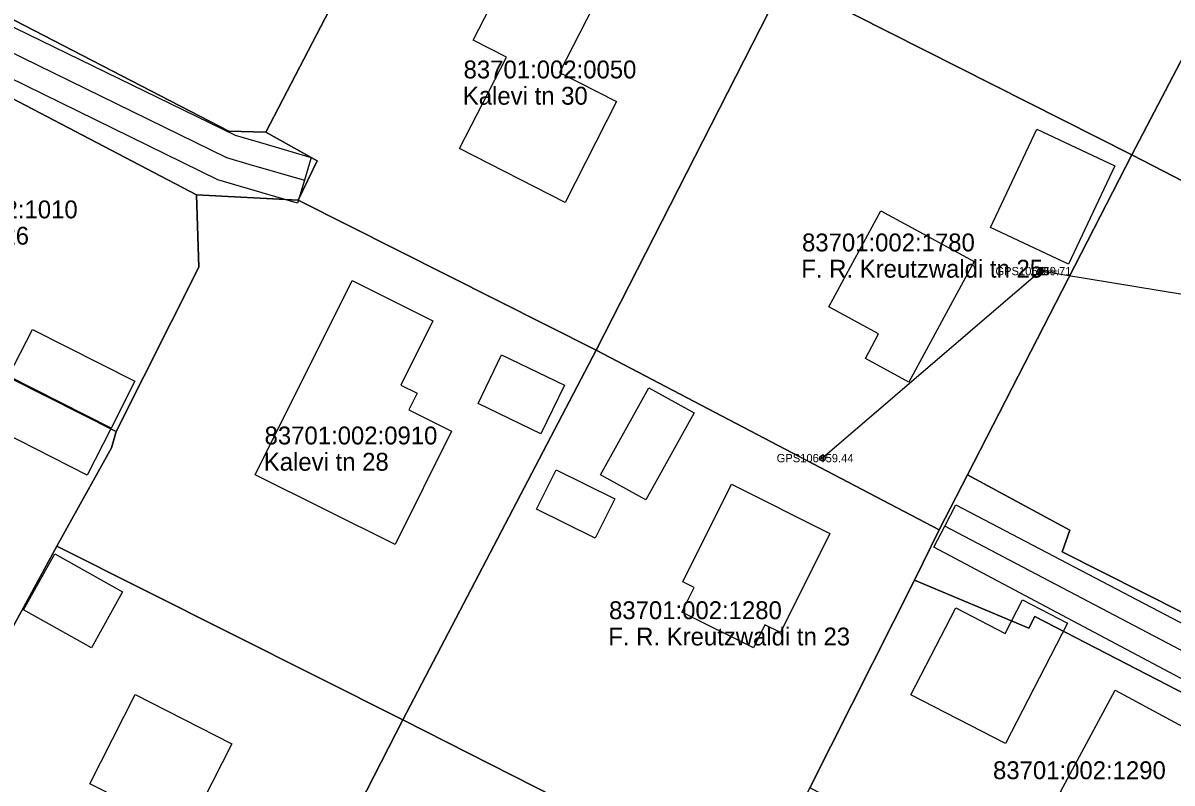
# Model space of a CAD drawing. Extents: x 580119 to 583377, y 6518915 to 6520820.
# Drawn here: x 581504.1 to 581600.6, y 6520162.8 to 6520226.6 of the extents above; entities that cross this region are included whole.
import ezdxf

# ---------------------------------------------------------------- set-up
doc = ezdxf.new("R2010")
doc.units = 0
for name, color, linetype in [('ELRAJATISMP', 7, 'Continuous'), ('Hoone Elu- või ühiskondlik hoone', 7, 'Continuous'), ('Hoone Kõrval- või tootmishoone', 7, 'Continuous'), ('L_AADRESS', 7, 'Continuous'), ('MAAMUDEL', 7, 'Continuous'), ('MOOTKORG-EH2000', 7, 'Continuous'), ('MOOTMPUNKT', 7, 'Continuous'), ('MOOTNR', 7, 'Continuous'), ('MPOHULIIN', 7, 'Continuous'), ('PIIR', 7, 'Continuous'), ('POST', 7, 'Continuous'), ('Tee Liiklusala', 7, 'Continuous'), ('Tee Tänav Kruuskate', 7, 'Continuous'), ('TUNNUS', 7, 'Continuous')]:
    doc.layers.add(name, color=color, linetype=linetype)

msp = doc.modelspace()

# ---------------------------------------------------------------- linework, layer by layer
at = {"layer": 'ELRAJATISMP'}
for p, q in [((581589.382, 6520206.077), (581589.382, 6520205.48)), ((581589.653, 6520206.077), (581589.653, 6520205.48))]:
    msp.add_line(p, q, dxfattribs=at)
msp.add_lwpolyline([(581588.92, 6520206.077), (581590.115, 6520206.077), (581590.115, 6520205.48), (581588.92, 6520205.48)], close=True, dxfattribs=at)
at = {"layer": 'Hoone Elu- või ühiskondlik hoone'}
for points in [[(581553.942, 6520220.01), (581549.621, 6520211.545), (581540.775, 6520216.062), (581544.698, 6520223.743), (581541.926, 6520225.158), (581545.709, 6520232.58), (581552.556, 6520229.093), (581549.17, 6520222.439)], [(581571.75, 6520202.781), (581576.13, 6520210.841), (581583.96, 6520206.591), (581578.47, 6520196.471), (581574.83, 6520198.452), (581575.94, 6520200.502)], [(581540.104, 6520192.346), (581535.37, 6520182.839), (581523.633, 6520188.67), (581531.752, 6520204.98), (581538.525, 6520201.619), (581535.842, 6520196.212), (581537.209, 6520195.533), (581536.508, 6520194.13)], [(581571.857, 6520183.763), (581567.692, 6520175.435), (581566.393, 6520176.078), (581565.433, 6520174.163), (581559.434, 6520177.161), (581560.47, 6520179.224), (581559.497, 6520179.705), (581563.596, 6520187.894)], [(581604.35, 6520165.985), (581597.897, 6520154.009), (581593.562, 6520156.341), (581595.422, 6520159.794), (581591.206, 6520162.073), (581595.796, 6520170.595)], [(581522.566, 6520157.552), (581517.928, 6520148.438), (581507.038, 6520153.985), (581511.137, 6520162.046), (581509.745, 6520162.757), (581513.559, 6520170.238), (581521.666, 6520166.106), (581518.401, 6520159.68)]]:
    msp.add_lwpolyline(points, close=True, dxfattribs=at)
at = {"layer": 'Hoone Kõrval- või tootmishoone'}
for points in [[(581595.754, 6520214.608), (581591.871, 6520206.359), (581585.333, 6520209.437), (581589.216, 6520217.686)], [(581511.532, 6520192.6), (581502.926, 6520196.95), (581504.922, 6520200.89), (581513.527, 6520196.541)], [(581542.321, 6520194.662), (581544.294, 6520198.751), (581549.579, 6520196.204), (581547.596, 6520192.112)], [(581511.532, 6520192.6), (581509.533, 6520188.652), (581500.929, 6520193.006), (581502.926, 6520196.95)], [(581552.613, 6520188.69), (581556.663, 6520195.98), (581560.453, 6520193.879), (581556.403, 6520186.589)], [(581547.236, 6520185.813), (581548.882, 6520189.111), (581553.79, 6520186.659), (581552.144, 6520183.36)], [(581512.501, 6520178.864), (581509.878, 6520174.17), (581504.174, 6520177.356), (581506.811, 6520182.049)], [(581591.796, 6520176.235), (581586.578, 6520166.126), (581578.641, 6520170.222), (581582.408, 6520177.522), (581586.569, 6520175.375), (581588.019, 6520178.184)]]:
    msp.add_lwpolyline(points, close=True, dxfattribs=at)
at = {"layer": 'MOOTMPUNKT'}
for centre in [(581589.517, 6520205.779), (581571.23, 6520190.084)]:
    msp.add_circle(centre, 0.1, dxfattribs=at)
at = {"layer": 'MPOHULIIN'}
msp.add_lwpolyline([(581646.487, 6520186.542), (581631.562, 6520198.859), (581589.517, 6520205.779), (581571.23, 6520190.084)], dxfattribs=at)
at = {"layer": 'PIIR'}
for points in [[(581583.97, 6520261.52), (581613.05, 6520246.51), (581610.93, 6520241.82), (581597.19, 6520215.53), (581568.1, 6520230.26)], [(581501.63, 6520251.7), (581524.76, 6520240.58), (581534.1, 6520235.9), (581524.52, 6520217.43), (581521.41, 6520217.52), (581491.96, 6520232.77)], [(581528.82, 6520215.03), (581524.52, 6520217.43), (581534.1, 6520235.9), (581538.79, 6520244.96), (581568.1, 6520230.26), (581552.23, 6520199.15), (581527.23, 6520211.74)], [(581610.93, 6520241.82), (581626.48, 6520236.22), (581644.07, 6520226.93), (581629.73, 6520198.75), (581597.19, 6520215.53)], [(581568.1, 6520230.26), (581597.19, 6520215.53), (581583.39, 6520188.69), (581581.01, 6520184.07), (581552.23, 6520199.15)], [(581489.39, 6520227.52), (581518.7, 6520212.19), (581518.89, 6520206.11), (581511.97, 6520192.31), (581479.44, 6520208.7)], [(581591.98, 6520184.05), (581583.39, 6520188.69), (581597.19, 6520215.53), (581629.73, 6520198.75), (581615.13, 6520170.23), (581591.33, 6520182.23)], [(581511.56, 6520190.95), (581511.97, 6520192.31), (581518.89, 6520206.11), (581518.7, 6520212.19), (581527.23, 6520211.74), (581552.23, 6520199.15), (581536.02, 6520168.12), (581506.99, 6520182.7)], [(581479.44, 6520208.7), (581511.97, 6520192.31), (581511.56, 6520190.95), (581506.99, 6520182.7), (581502.29, 6520174.04), (581470.18, 6520190.74)], [(581552.23, 6520199.15), (581581.01, 6520184.07), (581578.96, 6520179.83), (581570.17, 6520162.41), (581565.37, 6520153.21), (581536.02, 6520168.12)], [(581493.4, 6520156.77), (581502.29, 6520174.04), (581506.99, 6520182.7), (581536.02, 6520168.12), (581520.24, 6520137.28), (581491.13, 6520152.34)], [(581578.96, 6520179.83), (581588.53, 6520175.82), (581589.04, 6520176.78), (581612.12, 6520164.88), (581602.44, 6520145.86), (581570.17, 6520162.41)], [(581536.02, 6520168.12), (581565.37, 6520153.21), (581560.56, 6520143.98), (581551.54, 6520126.53), (581549.16, 6520122.21), (581520.24, 6520137.28)]]:
    msp.add_lwpolyline(points, close=True, dxfattribs=at)
for points in [[(581491.96, 6520232.77), (581521.41, 6520217.52), (581524.52, 6520217.43), (581528.82, 6520215.03), (581527.23, 6520211.74), (581518.7, 6520212.19), (581489.39, 6520227.52)], [(581612.12, 6520164.88), (581589.04, 6520176.78), (581588.53, 6520175.82), (581578.96, 6520179.83), (581581.01, 6520184.07), (581583.39, 6520188.69), (581591.98, 6520184.05), (581591.33, 6520182.23), (581615.13, 6520170.23)]]:
    msp.add_lwpolyline(points, dxfattribs=at)
at = {"layer": 'POST'}
for centre in [(581589.517, 6520205.779), (581571.23, 6520190.084)]:
    msp.add_circle(centre, 0.25, dxfattribs=at)
at = {"layer": 'Tee Liiklusala'}
for points in [[(581491.478, 6520232.04), (581521.93, 6520217.192), (581524.08, 6520216.562), (581528.31, 6520215.323), (581527.748, 6520213.404), (581527.186, 6520211.485), (581522.385, 6520212.891), (581520.478, 6520213.45), (581489.717, 6520228.51)], [(581612.91, 6520165.44), (581580.563, 6520182.613), (581581.493, 6520184.383), (581582.423, 6520186.153), (581615.778, 6520168.669)]]:
    msp.add_lwpolyline(points, dxfattribs=at)
at = {"layer": 'Tee Tänav Kruuskate'}
for points in [[(581484.21, 6520233.432), (581521.204, 6520215.321), (581523.093, 6520214.768), (581527.748, 6520213.404)], [(581620.46, 6520163.902), (581581.493, 6520184.383)]]:
    msp.add_lwpolyline(points, dxfattribs=at)

# ---------------------------------------------------------------- texts
at = {"layer": 'L_AADRESS'}
for s, p in [('Kalevi tn 30', (581541.047, 6520219.747)), ('Kalevi tn 26', (581494.163, 6520208.002)), ('F. R. Kreutzwaldi tn 25', (581569.447, 6520205.229)), ('Kalevi tn 28', (581524.347, 6520189.028)), ('F. R. Kreutzwaldi tn 23', (581553.252, 6520174.362))]:
    msp.add_text(s, height=1.5, dxfattribs=at).set_placement(p)
at = {"layer": 'MAAMUDEL'}
msp.add_text(' kaabel', height=0.35, dxfattribs=at).set_placement((581589.517, 6520205.604))
at = {"layer": 'MOOTKORG-EH2000'}
for s, p in [(' 59.71', (581589.517, 6520205.429)), (' 59.44', (581571.23, 6520189.734))]:
    msp.add_text(s, height=0.7, dxfattribs=at).set_placement(p)
at = {"layer": 'MOOTNR'}
for s, p in [('GPS1063 ', (581585.738, 6520205.429)), ('GPS1064 ', (581567.38, 6520189.734))]:
    msp.add_text(s, height=0.7, dxfattribs=at).set_placement(p)
at = {"layer": 'TUNNUS'}
for s, p in [('83701:002:0050', (581541.11, 6520221.952)), ('83701:002:1010', (581494.227, 6520210.207)), ('83701:002:1780', (581569.51, 6520207.434)), ('83701:002:0910', (581524.41, 6520191.233)), ('83701:002:1280', (581553.315, 6520176.567)), ('83701:002:1290', (581585.537, 6520163.137))]:
    msp.add_text(s, height=1.5, dxfattribs=at).set_placement(p)

doc.saveas('drawing.dxf')
